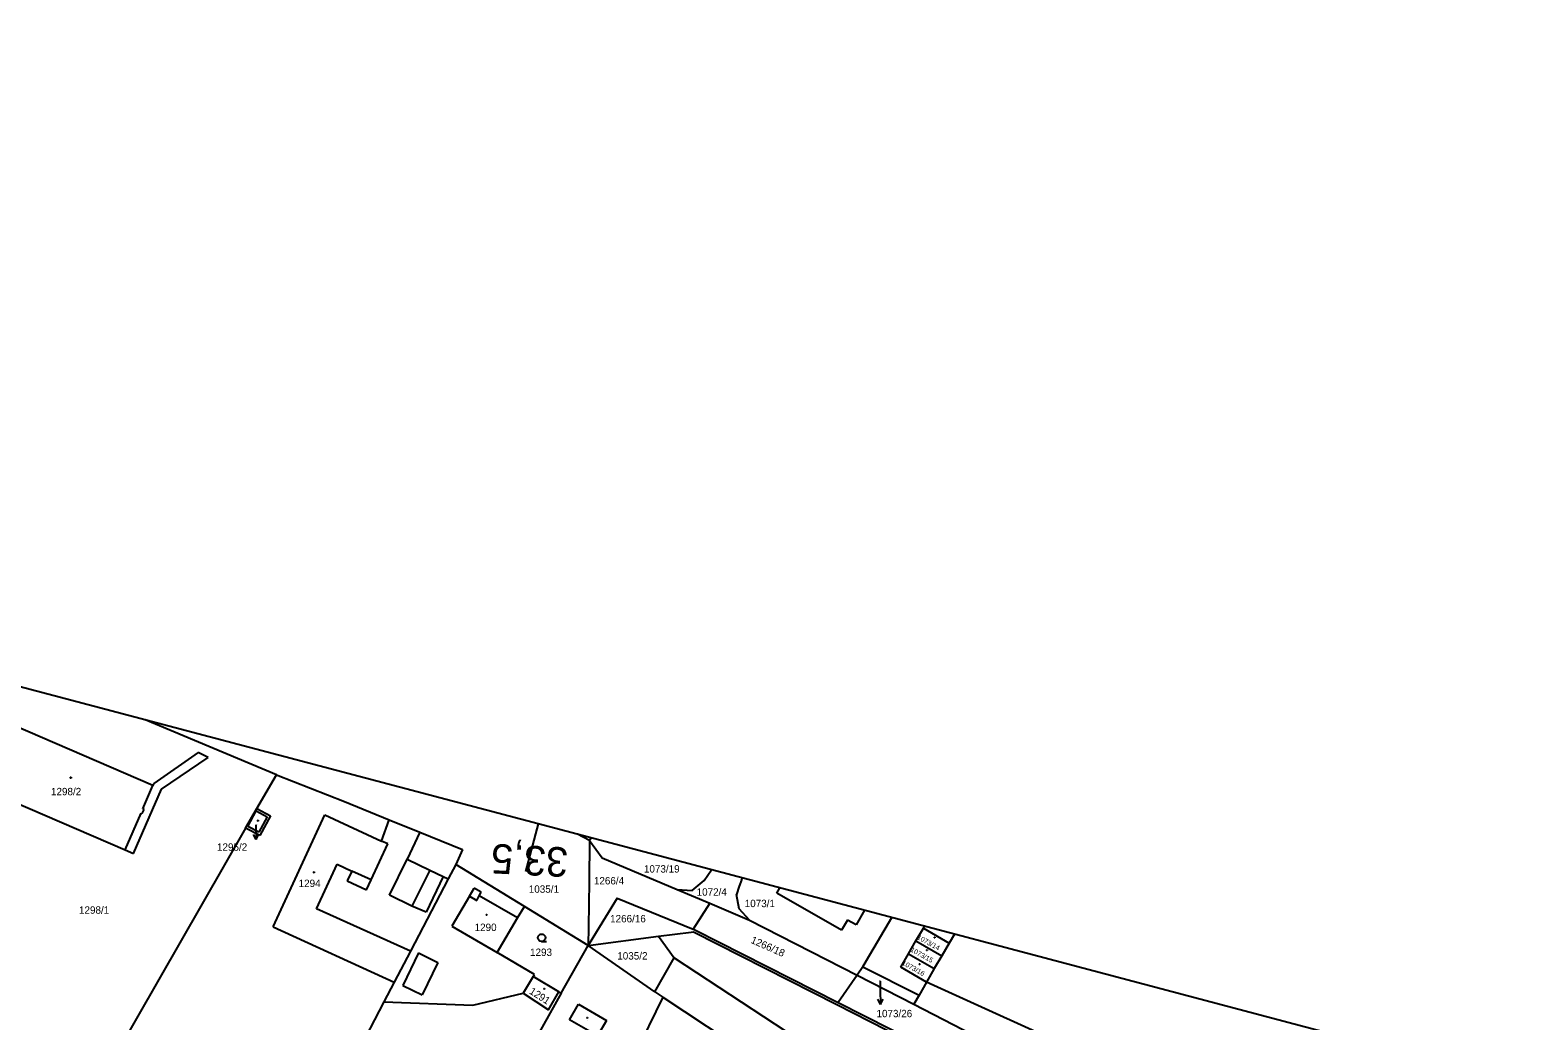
# Model space of a CAD drawing. Extents: x -805011 to -803920, y -1150790 to -1150234.
# Drawn here: x -804429.5 to -804123.3, y -1150435.6 to -1150234.4 of the extents above; entities that cross this region are included whole.
import ezdxf

# ---------------------------------------------------------------- set-up
doc = ezdxf.new("R2010")
doc.units = 0
for name, color, linetype in [('Default', 7, 'Continuous'), ('formát', 7, 'Continuous'), ('kilometráž - vrstava 7', 7, 'Continuous'), ('kn_celek - Cisla parcel pomocna', 7, 'Continuous'), ('kn_celek - Cisla pozemkovych parcel', 7, 'Continuous'), ('kn_celek - Cisla stavebnich parcel', 7, 'Continuous'), ('kn_celek - Hranice parcel', 7, 'Continuous'), ('kn_celek - Vnitrni kresby', 7, 'Continuous'), ('kn_celek - Znacky budov', 7, 'Continuous'), ('kn_celek - Znacky kultur', 7, 'Continuous')]:
    doc.layers.add(name, color=color, linetype=linetype)

# ---------------------------------------------------------------- blocks, each defined once
blk = doc.blocks.new('304')
at = {"layer": 'Default'}
blk.add_line((-0.1, 0), (9.9, 0), dxfattribs=at)
blk.add_circle((-0.1, 7.5), 7.5, dxfattribs=at)
blk = doc.blocks.new('402')
at = {"layer": 'Default'}
for p, q in [((-0.8, 0.8), (0.7, 0.8)), ((-0.8, 0.8), (-0.8, -0.7)), ((0.7, 0.8), (0.7, -0.7)), ((0.7, -0.7), (-0.8, -0.7))]:
    blk.add_line(p, q, dxfattribs=at)
blk = doc.blocks.new('Z61')
at = {"layer": 'Default'}
for p, q in [((0, 0), (30, 0)), ((30, 0), (19.2, 5.3)), ((30, 0), (19.2, -5.3))]:
    blk.add_line(p, q, dxfattribs=at)

msp = doc.modelspace()

# ---------------------------------------------------------------- linework, layer by layer
at = {"layer": 'formát'}
for p, q in [((-804326.3, -1150395.58), (-804935.34, -1150234.42)), ((-804326.3, -1150395.58), (-804328.86, -1150405.25)), ((-804123.29, -1150449.3), (-804326.3, -1150395.58))]:
    msp.add_line(p, q, dxfattribs=at)
at = {"layer": 'kn_celek - Cisla parcel pomocna'}
msp.add_line((-804256.86, -1150427.5), (-804256.83, -1150429.26), dxfattribs=at)
at = {"layer": 'kn_celek - Hranice parcel'}
for p, q in [((-804404.52, -1150387.76), (-804432.88, -1150375.5)), ((-804379.46, -1150385.59), (-804406.12, -1150374.46)), ((-804395.31, -1150381.08), (-804404.37, -1150387.39)), ((-804402.78, -1150388.51), (-804393.31, -1150382.07)), ((-804393.31, -1150382.07), (-804395.31, -1150381.08)), ((-804383.41, -1150392.47), (-804379.46, -1150385.59)), ((-804379.46, -1150385.59), (-804365.61, -1150391.04)), ((-804438.58, -1150388.63), (-804410.14, -1150400.87)), ((-804408.44, -1150401.61), (-804402.78, -1150388.51)), ((-804404.37, -1150387.39), (-804404.52, -1150387.76)), ((-804385.7, -1150396.46), (-804383.41, -1150392.47)), ((-804383.41, -1150392.47), (-804380.67, -1150393.93)), ((-804365.61, -1150391.04), (-804356.54, -1150394.72)), ((-804380.67, -1150393.93), (-804382.81, -1150397.95)), ((-804380.11, -1150416.46), (-804369.61, -1150393.75)), ((-804369.61, -1150393.75), (-804358.1, -1150399.06)), ((-804358.1, -1150399.06), (-804356.54, -1150394.72)), ((-804356.54, -1150394.72), (-804350.31, -1150397.25)), ((-804385.7, -1150396.46), (-804424.05, -1150463.28)), ((-804382.81, -1150397.95), (-804385.7, -1150396.46)), ((-804350.31, -1150397.25), (-804341.68, -1150400.75)), ((-804315.84, -1150398.95), (-804318.32, -1150397.69)), ((-804315.84, -1150398.95), (-804315.53, -1150398.43)), ((-804410.14, -1150400.87), (-804408.44, -1150401.61)), ((-804341.68, -1150400.75), (-804343.05, -1150403.79)), ((-804315.84, -1150398.95), (-804315.95, -1150407.27)), ((-804315.84, -1150398.95), (-804313.32, -1150402.44)), ((-804343.05, -1150403.79), (-804344.59, -1150406.74)), ((-804329.1, -1150412.32), (-804343.05, -1150403.79)), ((-804313.32, -1150402.44), (-804298.08, -1150408.89)), ((-804292.6, -1150407.09), (-804291.07, -1150404.9)), ((-804344.59, -1150406.74), (-804352.25, -1150421.43)), ((-804315.95, -1150407.27), (-804316.07, -1150416.45)), ((-804295, -1150409.08), (-804292.6, -1150407.09)), ((-804285.02, -1150406.97), (-804285.45, -1150408.22)), ((-804285.02, -1150406.97), (-804284.79, -1150406.57)), ((-804310.25, -1150410.69), (-804314.42, -1150417.49)), ((-804310.25, -1150410.69), (-804294.85, -1150416.94)), ((-804298.08, -1150408.89), (-804295, -1150409.08)), ((-804298.08, -1150408.89), (-804291.43, -1150411.7)), ((-804285.45, -1150408.22), (-804286.03, -1150409.89)), ((-804285.45, -1150412.79), (-804286.03, -1150409.89)), ((-804277.84, -1150409.62), (-804277.24, -1150408.57)), ((-804264.67, -1150417.17), (-804277.84, -1150409.62)), ((-804330.46, -1150414.66), (-804329.1, -1150412.32)), ((-804316.12, -1150420.26), (-804329.1, -1150412.32)), ((-804291.43, -1150411.7), (-804294.85, -1150416.94)), ((-804291.43, -1150411.7), (-804283.39, -1150415.1)), ((-804283.39, -1150415.1), (-804285.45, -1150412.79)), ((-804260.03, -1150413.12), (-804261.75, -1150416.09)), ((-804380.11, -1150416.46), (-804355.53, -1150427.71)), ((-804334.59, -1150421.71), (-804330.46, -1150414.66)), ((-804316.07, -1150416.45), (-804316.12, -1150420.26)), ((-804294.85, -1150416.94), (-804294.48, -1150417.09)), ((-804294.48, -1150417.09), (-804265.36, -1150431.82)), ((-804283.39, -1150415.1), (-804261.52, -1150426.31)), ((-804263.48, -1150415.09), (-804264.67, -1150417.17)), ((-804261.75, -1150416.09), (-804263.48, -1150415.09)), ((-804259.59, -1150423.33), (-804254.48, -1150414.59)), ((-804249.58, -1150419.32), (-804248.08, -1150416.74)), ((-804248.08, -1150416.74), (-804247.85, -1150416.34)), ((-804248.08, -1150416.74), (-804242.84, -1150419.78)), ((-804321.6, -1150429.95), (-804316.12, -1150420.26)), ((-804314.42, -1150417.49), (-804316.12, -1150420.26)), ((-804316.12, -1150420.26), (-804301.84, -1150418.4)), ((-804302.59, -1150429.69), (-804316.12, -1150420.26)), ((-804301.84, -1150418.4), (-804295.24, -1150417.53)), ((-804301.84, -1150418.4), (-804298.67, -1150422.8)), ((-804295.24, -1150417.53), (-804294.74, -1150417.47)), ((-804294.74, -1150417.47), (-804265.66, -1150432.25)), ((-804251.08, -1150421.93), (-804249.58, -1150419.32)), ((-804249.58, -1150419.32), (-804244.34, -1150422.36)), ((-804242.84, -1150419.78), (-804244.34, -1150422.36)), ((-804241.78, -1150417.95), (-804242.84, -1150419.78)), ((-804352.25, -1150421.43), (-804355.53, -1150427.71)), ((-804327.03, -1150426.13), (-804334.59, -1150421.71)), ((-804302.59, -1150429.69), (-804298.67, -1150422.8)), ((-804298.67, -1150422.8), (-804271.5, -1150440.64)), ((-804260.34, -1150424.61), (-804259.59, -1150423.33)), ((-804252.65, -1150424.64), (-804251.08, -1150421.93)), ((-804251.08, -1150421.93), (-804245.85, -1150424.97)), ((-804244.34, -1150422.36), (-804245.85, -1150424.97)), ((-804327.28, -1150426.55), (-804327.03, -1150426.13)), ((-804261.52, -1150426.31), (-804265.36, -1150431.82)), ((-804260.34, -1150424.61), (-804261.52, -1150426.31)), ((-804261.52, -1150426.31), (-804250.04, -1150432.2)), ((-804260.34, -1150424.61), (-804248.96, -1150430.34)), ((-804247.42, -1150427.68), (-804252.65, -1150424.64)), ((-804245.85, -1150424.97), (-804247.42, -1150427.68)), ((-804355.53, -1150427.71), (-804357.62, -1150431.72)), ((-804327.28, -1150426.55), (-804329.31, -1150429.92)), ((-804322.08, -1150429.66), (-804327.28, -1150426.55)), ((-804247.42, -1150427.68), (-804248.96, -1150430.34)), ((-804208.87, -1150445.2), (-804247.42, -1150427.68)), ((-804357.62, -1150431.72), (-804373.69, -1150462.54)), ((-804357.62, -1150431.72), (-804339.57, -1150432.36)), ((-804339.57, -1150432.36), (-804329.31, -1150429.92)), ((-804321.6, -1150429.95), (-804338.65, -1150460.11)), ((-804329.31, -1150429.92), (-804324.23, -1150433.31)), ((-804324.23, -1150433.31), (-804322.08, -1150429.66)), ((-804322.08, -1150429.66), (-804321.6, -1150429.95)), ((-804319.91, -1150435.33), (-804318.09, -1150432.21)), ((-804318.09, -1150432.21), (-804312.41, -1150435.5)), ((-804301, -1150430.74), (-804317.22, -1150463.88)), ((-804302.59, -1150429.69), (-804301, -1150430.74)), ((-804301, -1150430.74), (-804226.72, -1150479.76)), ((-804265.66, -1150432.25), (-804238.71, -1150445.94)), ((-804265.36, -1150431.82), (-804239.5, -1150444.89)), ((-804248.96, -1150430.34), (-804250.04, -1150432.2)), ((-804250.04, -1150432.2), (-804236.02, -1150439.39)), ((-804314.22, -1150438.61), (-804319.91, -1150435.33)), ((-804312.41, -1150435.5), (-804314.22, -1150438.61))]:
    msp.add_line(p, q, dxfattribs=at)
at = {"layer": 'kn_celek - Vnitrni kresby'}
for p, q in [((-804406.59, -1150392.54), (-804404.52, -1150387.76)), ((-804406.7, -1150393.48), (-804406.34, -1150392.65)), ((-804406.34, -1150392.65), (-804406.59, -1150392.54)), ((-804410.14, -1150400.87), (-804406.95, -1150393.37)), ((-804406.95, -1150393.37), (-804406.7, -1150393.48)), ((-804385.25, -1150396.11), (-804383.55, -1150392.95)), ((-804383.55, -1150392.95), (-804381.35, -1150394.14)), ((-804381.35, -1150394.14), (-804383.05, -1150397.28)), ((-804383.05, -1150397.28), (-804385.25, -1150396.11)), ((-804350.31, -1150397.25), (-804352.9, -1150402.77)), ((-804360.18, -1150406.92), (-804356.83, -1150399.64)), ((-804356.83, -1150399.64), (-804358.1, -1150399.06)), ((-804371.32, -1150412.82), (-804367.53, -1150404.64)), ((-804367.53, -1150404.64), (-804367.13, -1150403.78)), ((-804367.13, -1150403.78), (-804364.13, -1150405.16)), ((-804356.49, -1150410.04), (-804352.9, -1150402.77)), ((-804352.9, -1150402.77), (-804348.33, -1150404.96)), ((-804348.33, -1150404.96), (-804351.92, -1150412.31)), ((-804348.33, -1150404.96), (-804345.6, -1150406.27)), ((-804364.13, -1150405.16), (-804365.07, -1150407.16)), ((-804365.07, -1150407.16), (-804361.13, -1150408.99)), ((-804360.18, -1150406.92), (-804364.13, -1150405.16)), ((-804361.13, -1150408.99), (-804360.18, -1150406.92)), ((-804345.6, -1150406.27), (-804349.04, -1150413.47)), ((-804345.6, -1150406.27), (-804344.59, -1150406.74)), ((-804351.92, -1150412.31), (-804356.49, -1150410.04)), ((-804340.24, -1150410.24), (-804343.86, -1150416.31)), ((-804340.24, -1150410.24), (-804339.3, -1150408.66)), ((-804340.24, -1150410.24), (-804338.78, -1150411.1)), ((-804337.85, -1150409.43), (-804339.3, -1150408.66)), ((-804338.78, -1150411.1), (-804338.31, -1150410.16)), ((-804338.31, -1150410.16), (-804337.85, -1150409.43)), ((-804330.46, -1150414.66), (-804338.31, -1150410.16)), ((-804352.25, -1150421.43), (-804371.32, -1150412.82)), ((-804349.04, -1150413.47), (-804351.92, -1150412.31)), ((-804343.86, -1150416.31), (-804334.59, -1150421.71)), ((-804350.61, -1150421.76), (-804353.77, -1150428.38)), ((-804350.61, -1150421.76), (-804346.64, -1150423.73)), ((-804346.64, -1150423.73), (-804349.83, -1150430.26)), ((-804353.77, -1150428.38), (-804349.83, -1150430.26))]:
    msp.add_line(p, q, dxfattribs=at)

# ---------------------------------------------------------------- block references
at = {"layer": 'kn_celek - Cisla parcel pomocna'}
for p, xscale, yscale, rotation in [((-804383.65, -1150395.78), 0.1, 0.10000000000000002, -87.95448000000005), ((-804256.83, -1150429.26), 0.09999999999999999, 0.10000000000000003, -89.03709000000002)]:
    msp.add_blockref('Z61', p, dxfattribs=dict(at, xscale=xscale, yscale=yscale, rotation=rotation))
at = {"layer": 'kn_celek - Znacky budov', "xscale": 0.1, "yscale": 0.10000000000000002}
for p in [(-804421.23, -1150386.2), (-804383.22, -1150394.93), (-804371.87, -1150405.41), (-804336.79, -1150414.06), (-804245.81, -1150418.63), (-804247.34, -1150421.22), (-804248.87, -1150424.06), (-804325.07, -1150429.08), (-804316.35, -1150434.96)]:
    msp.add_blockref('402', p, dxfattribs=at)
at = {"layer": 'kn_celek - Znacky kultur', "xscale": 0.1, "yscale": 0.10000000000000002}
msp.add_blockref('304', (-804325.58, -1150419.44), dxfattribs=at)

# ---------------------------------------------------------------- texts
at = {"layer": 'kilometráž - vrstava 7'}
msp.add_text('33,5', height=6, rotation=177.0919, dxfattribs=at).set_placement((-804320.1, -1150400.4))
at = {"layer": 'kn_celek - Cisla parcel pomocna'}
for s, p in [('1295/2', (-804391.52, -1150401.03)), ('1073/26', (-804257.59, -1150434.83))]:
    msp.add_text(s, height=1.5, dxfattribs=at).set_placement(p)
at = {"layer": 'kn_celek - Cisla pozemkovych parcel'}
for s, height, p in [('1073/19', 1.5, (-804304.82, -1150405.46)), ('1035/1', 1.5, (-804328.2, -1150409.56)), ('1266/4', 1.5, (-804314.98, -1150407.87)), ('1072/4', 1.5, (-804294.12, -1150410.15)), ('1073/1', 1.5, (-804284.35, -1150412.48)), ('1298/1', 1.5, (-804419.54, -1150413.82)), ('1266/16', 1.5, (-804311.69, -1150415.57)), ('1293', 1.5, (-804327.95, -1150422.39)), ('1035/2', 1.5, (-804310.23, -1150423.12)), ('1073/26', 0.1, (-804257.17, -1150427.47))]:
    msp.add_text(s, height=height, dxfattribs=at).set_placement(p)
msp.add_text('1266/18', height=1.5, rotation=336.1603, dxfattribs=at).set_placement((-804283.26, -1150419.69))
at = {"layer": 'kn_celek - Cisla stavebnich parcel'}
for s, height, p in [('1298/2', 1.5, (-804425.23, -1150389.76)), ('1295/2', 0.1, (-804383.65, -1150395.75)), ('1294', 1.5, (-804374.94, -1150408.39)), ('1290', 1.5, (-804339.2, -1150417.32)), ('1278/2', 0.1, (-804316.32, -1150435.55))]:
    msp.add_text(s, height=height, dxfattribs=at).set_placement(p)
for s, height, rotation, p in [('1073/14', 1, 331.2, (-804249.44, -1150418.9)), ('1073/15', 1, 331.2, (-804250.81, -1150421.42)), ('1073/16', 1, 331.2, (-804252.53, -1150424.11)), ('1291', 1.5, 327.6, (-804328.24, -1150429.93))]:
    msp.add_text(s, height=height, rotation=rotation, dxfattribs=at).set_placement(p)

doc.saveas('drawing.dxf')
